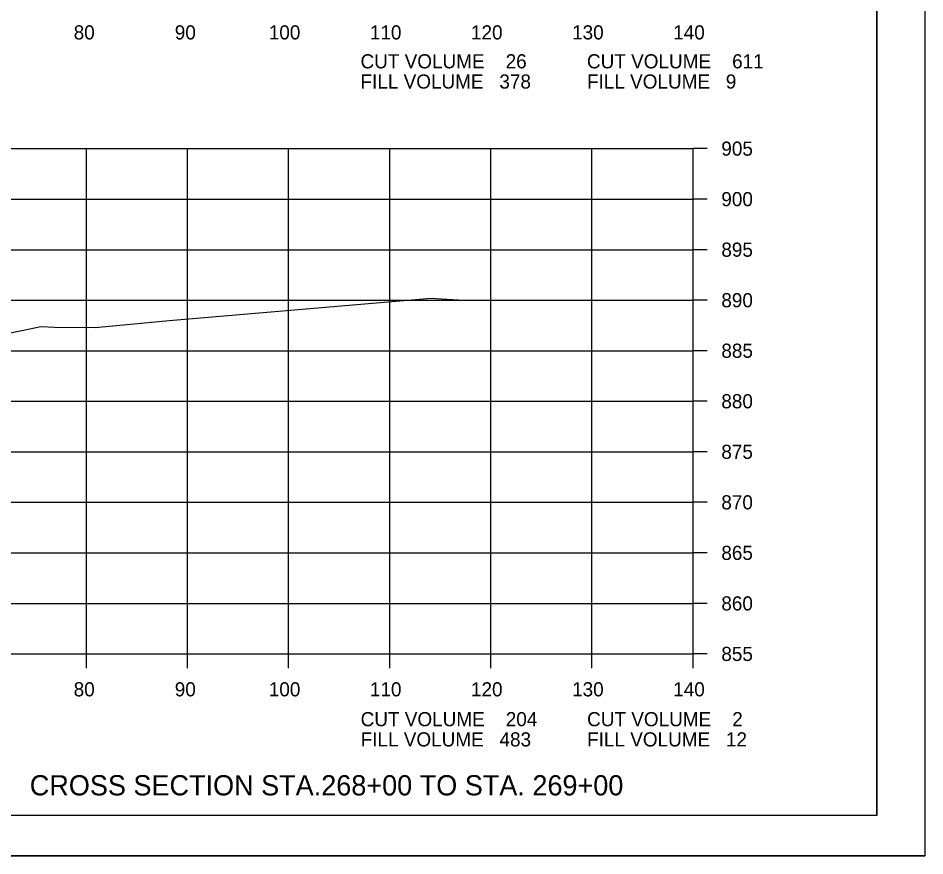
# Model space of a CAD drawing. Extents: x 1486524 to 1499135, y 326561 to 337924.
# Drawn here: x 1489056.1 to 1489145.8, y 330005.9 to 330088.8 of the extents above; entities that cross this region are included whole.
import ezdxf

# ---------------------------------------------------------------- set-up
doc = ezdxf.new("R2010")
doc.units = 0
for name, color, linetype in [('E_Const Align', 7, 'Continuous'), ('E_Const Align Station', 7, 'Continuous'), ('E_Ownership Information', 7, 'Continuous'), ('E_Property Line', 7, 'Continuous'), ('E_Proposed ROW Fig Annot', 7, 'Continuous'), ('E_Quarter Calls', 7, 'Continuous'), ('E_Tract Number', 7, 'Continuous')]:
    doc.layers.add(name, color=color, linetype=linetype)

msp = doc.modelspace()

# ---------------------------------------------------------------- linework, layer by layer
at = {"layer": 'E_Const Align'}
for p, q in [((1489122.885, 330025.895), (1489122.885, 330075.895)), ((1489124.285, 330075.895), (1489122.885, 330075.895)), ((1489124.285, 330070.895), (1489122.885, 330070.895)), ((1489124.285, 330065.895), (1489122.885, 330065.895)), ((1489124.285, 330060.895), (1489122.885, 330060.895)), ((1489124.285, 330055.895), (1489122.885, 330055.895)), ((1489124.285, 330050.895), (1489122.885, 330050.895)), ((1489124.285, 330045.895), (1489122.885, 330045.895)), ((1489124.285, 330040.895), (1489122.885, 330040.895)), ((1489124.285, 330035.895), (1489122.885, 330035.895)), ((1489124.285, 330030.895), (1489122.885, 330030.895)), ((1488842.885, 330025.895), (1489122.885, 330025.895)), ((1489062.885, 330024.495), (1489062.885, 330025.895)), ((1489072.885, 330024.495), (1489072.885, 330025.895)), ((1489082.885, 330024.495), (1489082.885, 330025.895)), ((1489092.885, 330024.495), (1489092.885, 330025.895)), ((1489102.885, 330024.495), (1489102.885, 330025.895)), ((1489112.885, 330024.495), (1489112.885, 330025.895)), ((1489122.885, 330024.495), (1489122.885, 330025.895)), ((1489124.285, 330025.895), (1489122.885, 330025.895))]:
    msp.add_line(p, q, dxfattribs=at)
at = {"layer": 'E_Ownership Information'}
for p, q in [((1488842.885, 330075.895), (1489122.885, 330075.895)), ((1489062.885, 330025.895), (1489062.885, 330075.895)), ((1489072.885, 330025.895), (1489072.885, 330075.895)), ((1489082.885, 330025.895), (1489082.885, 330075.895)), ((1489092.885, 330025.895), (1489092.885, 330075.895)), ((1489102.885, 330025.895), (1489102.885, 330075.895)), ((1489112.885, 330025.895), (1489112.885, 330075.895)), ((1489122.885, 330025.895), (1489122.885, 330075.895)), ((1488842.885, 330070.895), (1489122.885, 330070.895)), ((1488842.885, 330065.895), (1489122.885, 330065.895)), ((1488842.885, 330060.895), (1489122.885, 330060.895)), ((1488842.885, 330055.895), (1489122.885, 330055.895)), ((1488842.885, 330050.895), (1489122.885, 330050.895)), ((1488842.885, 330045.895), (1489122.885, 330045.895)), ((1488842.885, 330040.895), (1489122.885, 330040.895)), ((1488842.885, 330035.895), (1489122.885, 330035.895)), ((1488842.885, 330030.895), (1489122.885, 330030.895)), ((1488842.885, 330025.895), (1489122.885, 330025.895))]:
    msp.add_line(p, q, dxfattribs=at)
at = {"layer": 'E_Property Line'}
for q in [(1489141.065, 330215.355), (1488824.885, 330009.895)]:
    msp.add_line((1489141.065, 330009.895), q, dxfattribs=at)
at = {"layer": 'E_Quarter Calls'}
msp.add_line((1488812.485, 330005.916), (1489145.818, 330005.916), dxfattribs=at)
for points in [[(1488812.478, 330219.25), (1489145.818, 330219.25), (1489145.818, 330005.912), (1488812.478, 330005.912)], [(1489058.805, 330215.355), (1489058.805, 330205.475), (1489094.538, 330205.475), (1489094.538, 330202.555), (1489117.737, 330202.555), (1489117.737, 330178.222), (1489141.065, 330178.222), (1489141.065, 330009.895), (1488824.885, 330009.895), (1488824.885, 330215.355)]]:
    msp.add_lwpolyline(points, close=True, dxfattribs=at)
at = {"layer": 'E_Tract Number'}
msp.add_lwpolyline([(1489049.18, 330056.455), (1489056.647, 330057.916), (1489058.375, 330058.288), (1489059.713, 330058.223), (1489063.744, 330058.179), (1489071.444, 330058.907), (1489071.454, 330058.908), (1489071.454, 330058.908), (1489071.469, 330058.909), (1489096.604, 330061.055), (1489097.128, 330061.086), (1489097.493, 330061.061), (1489099.693, 330060.923), (1489100.15, 330060.895)], dxfattribs=at)

# ---------------------------------------------------------------- texts
at = {"layer": 'E_Const Align Station'}
for s, p in [('80', (1489061.624, 330086.695)), ('90', (1489071.624, 330086.695)), ('100', (1489080.924, 330086.695)), ('110', (1489090.924, 330086.695)), ('120', (1489100.924, 330086.695)), ('130', (1489110.924, 330086.695)), ('140', (1489120.924, 330086.695)), ('CUT VOLUME    26 ', (1489089.996, 330083.834)), ('CUT VOLUME    611', (1489112.396, 330083.834)), ('FILL VOLUME   378', (1489089.996, 330081.834)), ('FILL VOLUME   9', (1489112.396, 330081.834)), ('905', (1489125.685, 330075.195)), ('900', (1489125.685, 330070.195)), ('895', (1489125.685, 330065.195)), ('890', (1489125.685, 330060.195)), ('885', (1489125.685, 330055.195)), ('880', (1489125.685, 330050.195)), ('875', (1489125.685, 330045.195)), ('870', (1489125.685, 330040.195)), ('865', (1489125.685, 330035.195)), ('860', (1489125.685, 330030.195)), ('855', (1489125.685, 330025.195)), ('80', (1489061.624, 330021.695)), ('90', (1489071.624, 330021.695)), ('100', (1489080.924, 330021.695)), ('110', (1489090.924, 330021.695)), ('120', (1489100.924, 330021.695)), ('130', (1489110.924, 330021.695)), ('140', (1489120.924, 330021.695)), ('CUT VOLUME    204', (1489090.01, 330018.738)), ('CUT VOLUME    2', (1489112.41, 330018.738)), ('FILL VOLUME   483', (1489090.01, 330016.738)), ('FILL VOLUME   12', (1489112.41, 330016.738))]:
    msp.add_text(s, height=1.4, dxfattribs=at).set_placement(p)
at = {"layer": 'E_Proposed ROW Fig Annot'}
msp.add_text('CROSS SECTION STA.268+00 TO STA. 269+00', height=2, dxfattribs=at).set_placement((1489057.282, 330011.895))

doc.saveas('drawing.dxf')
